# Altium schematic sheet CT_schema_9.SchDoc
size 391 x 238 mm
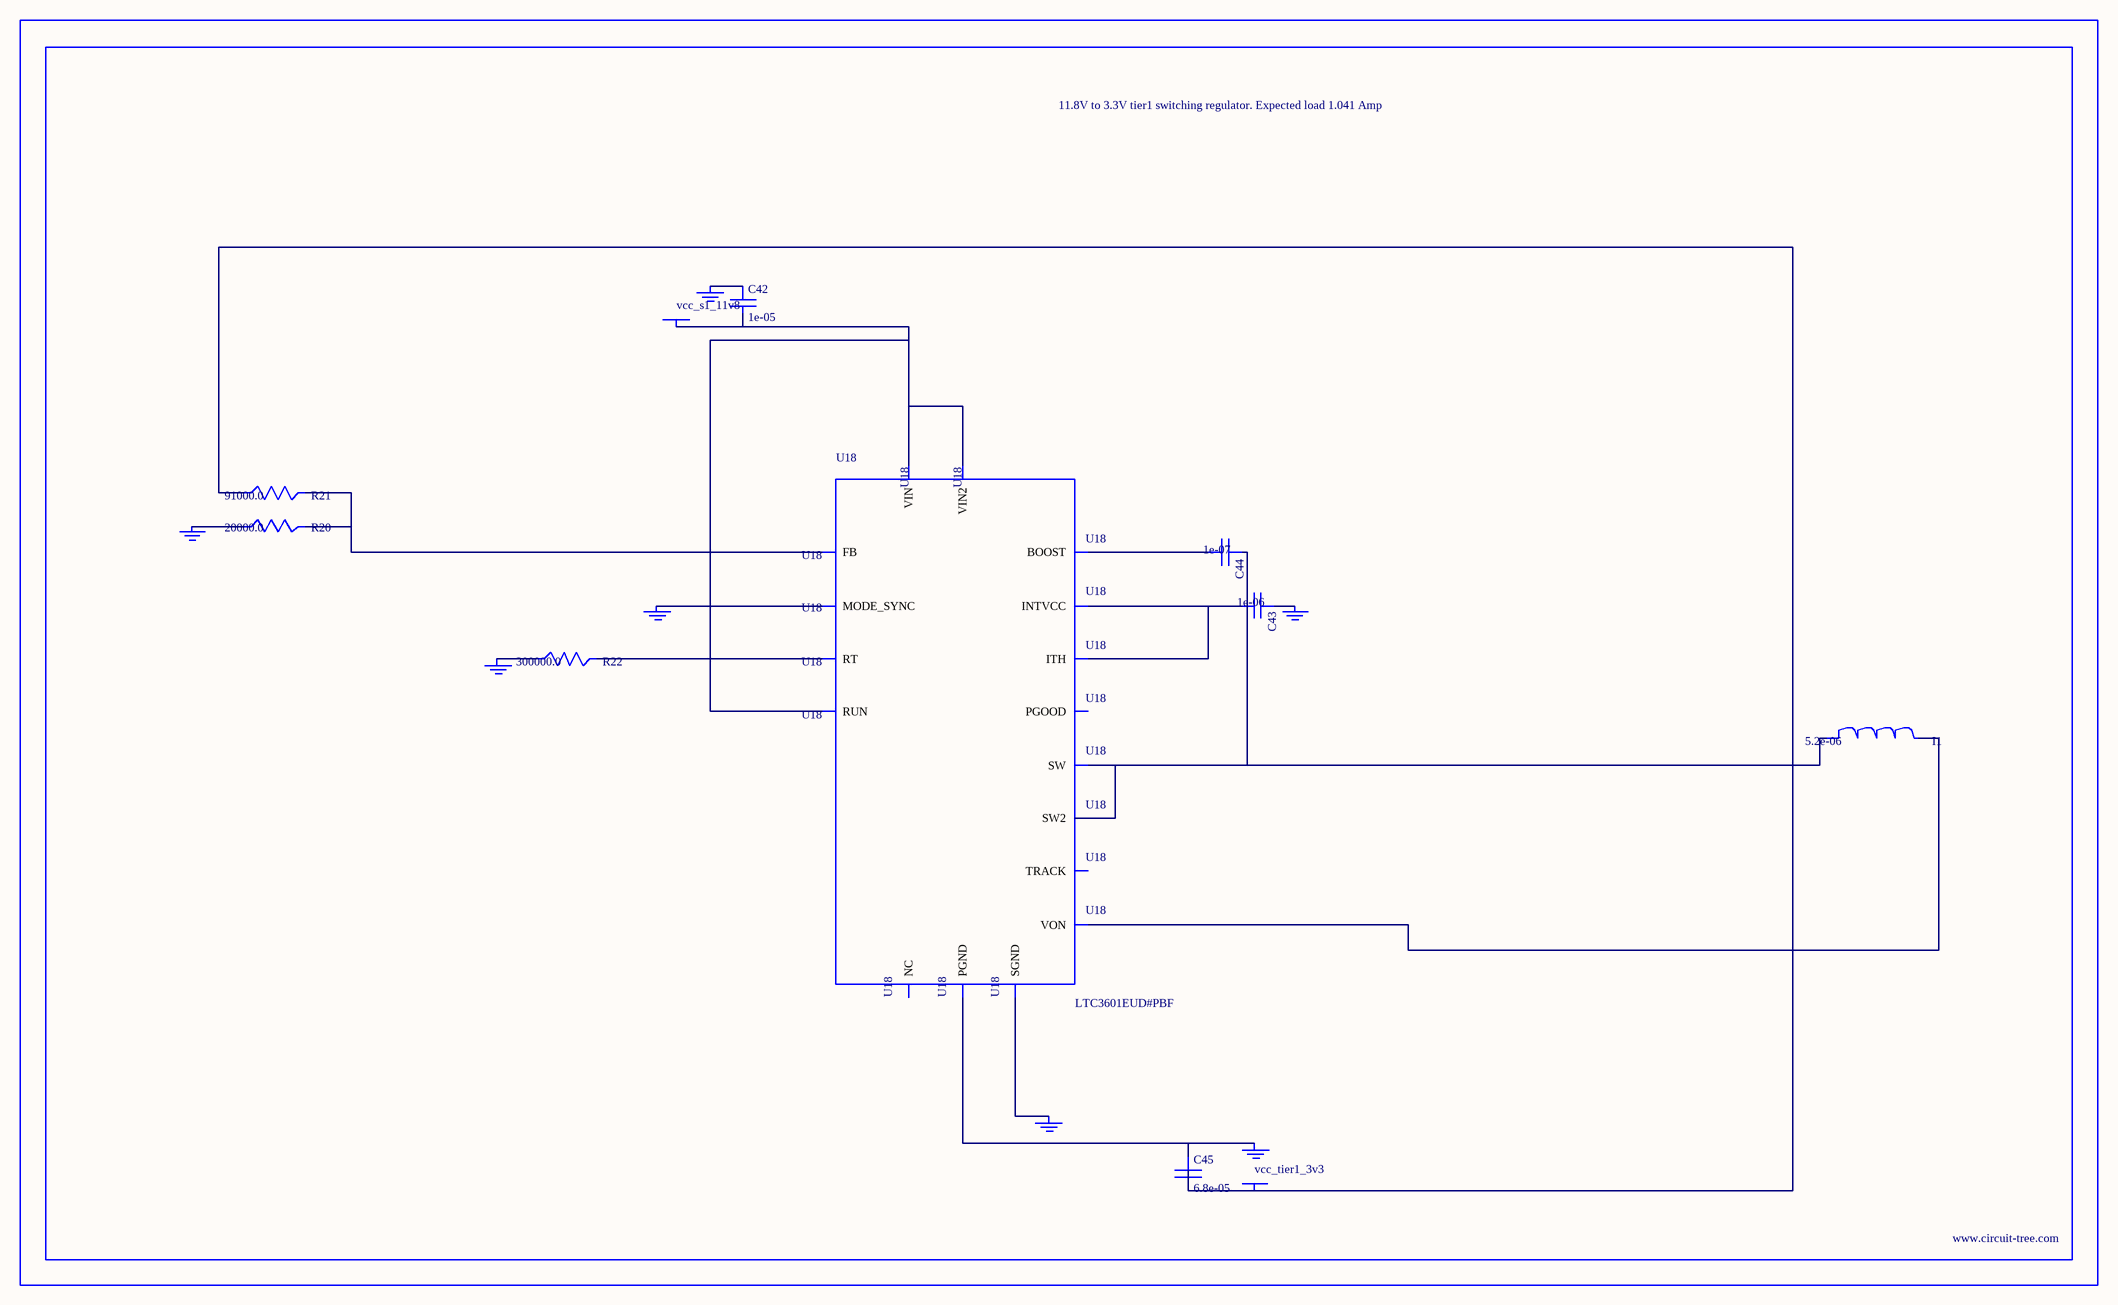
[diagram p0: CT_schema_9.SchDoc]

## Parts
BORDER8  (no value)
C42  1e-05  [C0805]
C43  1e-06  [C0603]
C44  1e-07  [C0402]
C45  6.8e-05  [2220]
GND_INSTANCE_8_0  (no value)
GND_INSTANCE_8_1  (no value)
GND_INSTANCE_8_2  (no value)
GND_INSTANCE_8_3  (no value)
GND_INSTANCE_8_4  (no value)
GND_INSTANCE_8_5  (no value)
GND_INSTANCE_8_6  (no value)
I1  5.2e-06  [DR1040]
POWER_INSTANCE_8_0  vcc_s1_11v8
POWER_INSTANCE_8_1  vcc_tier1_3v3
R20  20000.0  [R0603]
R21  91000.0  [R0603]
R22  300000.0  [R0603]
U18  LTC3601EUD#PBF  [QFN-16_EP]

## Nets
NetC42_1: C42.1 GND_INSTANCE_8_5.0(GND)
NetC42_2: C42.2 POWER_INSTANCE_8_0.0(PWR) U18.14(RUN) U18.15(VIN) U18.16(VIN2)
NetC43_1: C43.1 GND_INSTANCE_8_1.0(GND)
NetC43_2: C43.2 U18.7(INTVCC) U18.12(ITH)
NetC44_1: C44.1 I1.1 U18.3(SW) U18.4(SW2)
NetC44_2: C44.2 U18.6(BOOST)
NetC45_1: C45.1 GND_INSTANCE_8_6.0(GND) U18.17(PGND)
NetC45_2: C45.2 I1.2 POWER_INSTANCE_8_1.0(PWR) R21.1 U18.8(VON)
NetGND_INSTANCE_8_0_0: GND_INSTANCE_8_0.0(GND) U18.1(MODE_SYNC)
NetGND_INSTANCE_8_2_0: GND_INSTANCE_8_2.0(GND) U18.9(SGND)
NetGND_INSTANCE_8_3_0: GND_INSTANCE_8_3.0(GND) R22.1
NetGND_INSTANCE_8_4_0: GND_INSTANCE_8_4.0(GND) R20.1
NetR20_2: R20.2 R21.2 U18.11(FB)
NetR22_2: R22.2 U18.10(RT)

Not connected (* = marked no-connect by the designer): U18 2(PGOOD) 5(NC) 13(TRACK)

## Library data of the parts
BORDER8 = BORDER_PAGE8
C42 = C0805C106K8RACTU
C43 = C0603C105K3RACTU
C44 = C0402C104K3RACTU
C45 = C5750X5R1A686M
GND_INSTANCE_8_0-GND_INSTANCE_8_6 = GND
I1 = DR1040-5R2-R
POWER_INSTANCE_8_0 POWER_INSTANCE_8_1 = PWR
R20 = RC0603JR-0720KL
R21 = RC0603JR-0791KL
R22 = RC0603JR-07300KL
